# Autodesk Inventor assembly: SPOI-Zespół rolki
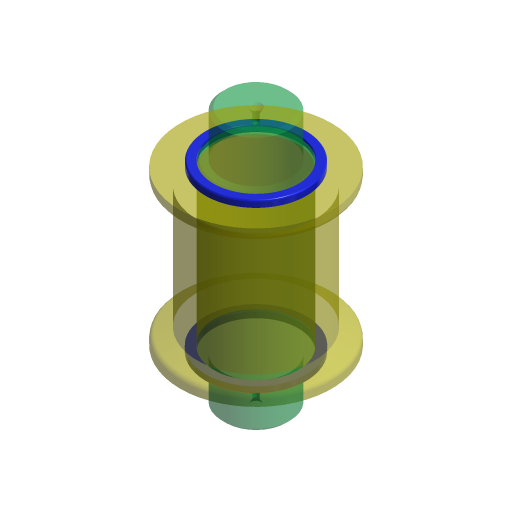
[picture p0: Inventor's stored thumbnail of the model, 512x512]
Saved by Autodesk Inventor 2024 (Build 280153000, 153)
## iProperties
Company: ATC
Shininess: 20.0
Length Units: 11269
Angle Units: 11279
Time Units: 11290
Mass Units: 11283
Length Display Precision: 3
Angle Display Precision: 2
Compacted: True
Created: 2023-03
Part Number: SPOI-Zespół rolki
Document SubType Name: Assembly
Designer: Andrzej Jaskulski
Mass: 60.2464 g
Surface Area: 198.901 cm^2
Volume: 60.2464 cm^3
Density: 1 g/cm^3
Checked By: A.J.
Engr Approved By: Andrzej Jaskulski
Mfg Approved By: Andrzej Jaskulski
Authority: A.J.
Description: Wg ZN-07/2008
Density: 0.0
Volumn: 0.0
Area: 0.0
PropertySet Name: Model Information
Control State: 0
Master: False
Checked Out: False
Title: A.J.: Kurs R2024-MEP
Author: Andrzej Jaskulski
Revision Number: 1/24
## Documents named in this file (4)
- C:\Users\AndJas\Documents\R2024-MEP\Obszar roboczy\SPOI-Zespół rolki.iam
- C:\Users\AndJas\Documents\R2024-MEP\Obszar roboczy\SPOI--Wałek.ipt
- C:\Users\AndJas\Documents\R2024-MEP\Obszar roboczy\SPOI--Podkładka.ipt
- C:\Users\AndJas\Documents\R2024-MEP\Obszar roboczy\SPOI--Rolka.ipt
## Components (4 placed, 3 different names)
1. SPOI--Wałek:1 — Wstawiające:3
2. SPOI--Podkładka:1 — Wstawiające:2, Wstawiające:3
3. SPOI--Podkładka:2 — Wstawiające:1
4. SPOI--Rolka:1 — Wstawiające:1, Wstawiające:2
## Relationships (3: Insert 3)
- Wstawiające:1 [Insert]: SPOI--Podkładka:2 ↔ SPOI--Rolka:1
- Wstawiające:2 [Insert]: SPOI--Podkładka:1 ↔ SPOI--Rolka:1
- Wstawiające:3 [Insert]: SPOI--Wałek:1 ↔ SPOI--Podkładka:1
